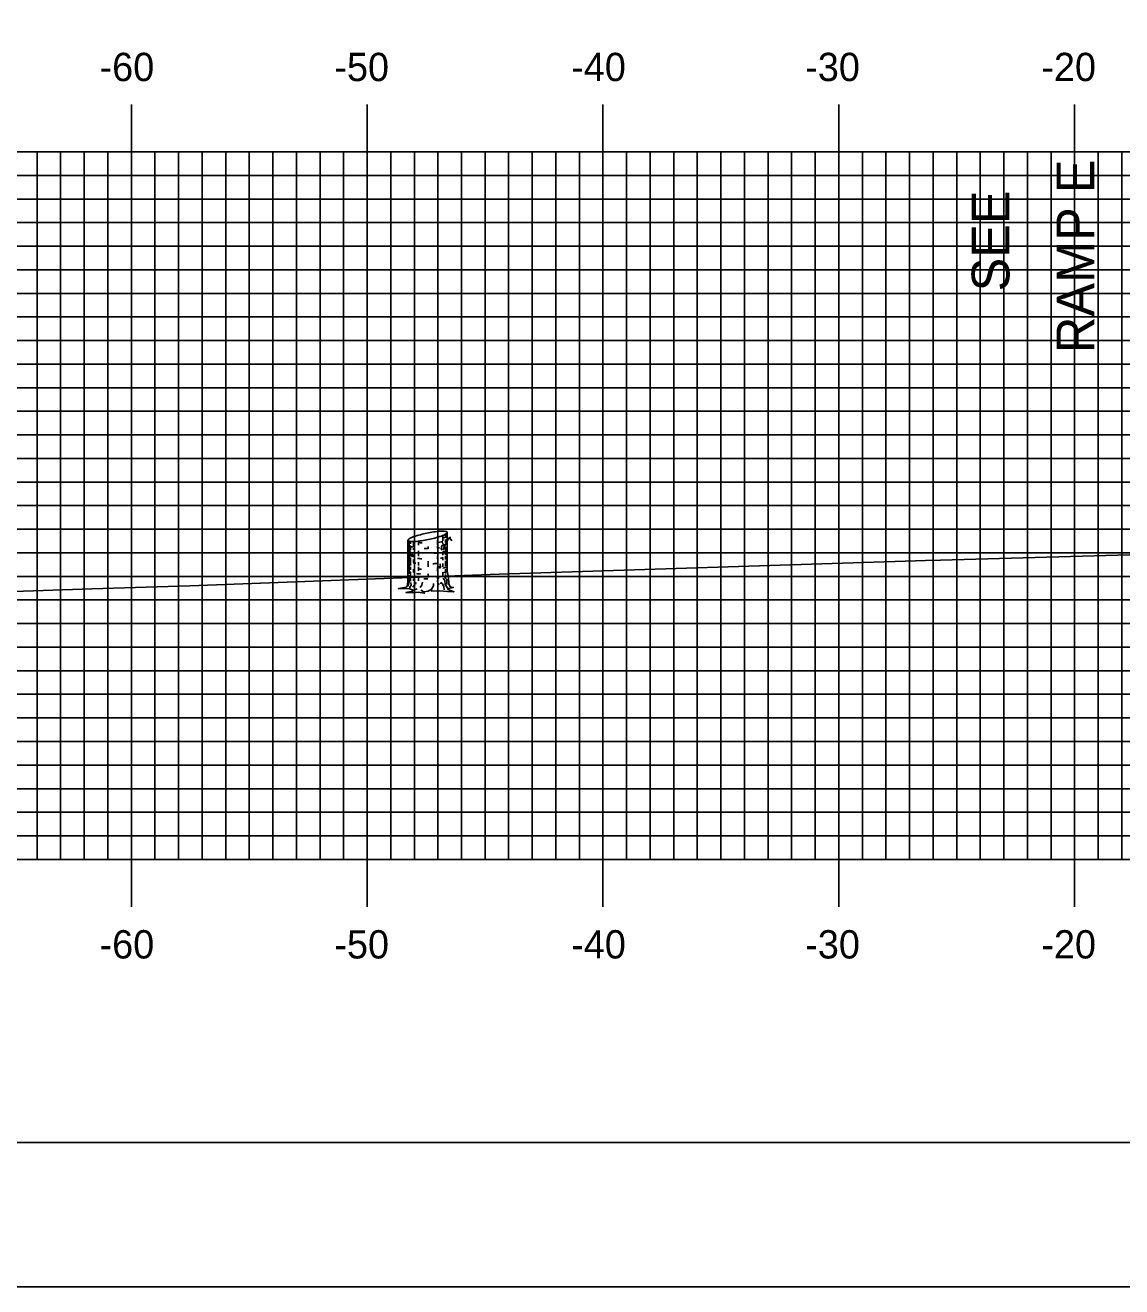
# Model space of a CAD drawing. Extents: x 1666 to 2009, y -1658 to -1438.
# Drawn here: x 1767.2 to 1813.7, y -1657.7 to -1604.2 of the extents above; entities that cross this region are included whole.
import ezdxf

# ---------------------------------------------------------------- set-up
doc = ezdxf.new("R2010")
doc.units = 0
for name, color, linetype in [('ANNOTATION', 7, 'Continuous'), ('BORDER', 7, 'Continuous'), ('H_V ANNOTATION', 7, 'Continuous'), ('M_Trees_Conifer_Pay', 7, 'Continuous'), ('MAJOR', 7, 'Continuous'), ('MINOR', 7, 'Continuous'), ('PLOT BOUNDARY', 7, 'Continuous'), ('S_Roadway_Centerline', 7, 'Continuous')]:
    doc.layers.add(name, color=color, linetype=linetype)

msp = doc.modelspace()

# ---------------------------------------------------------------- linework, layer by layer
at = {"layer": 'BORDER'}
msp.add_lwpolyline([(1682.074, -1651.604), (2002.074, -1651.604), (2002.074, -1441.604), (1682.074, -1441.604)], close=True, dxfattribs=at)
at = {"layer": 'M_Trees_Conifer_Pay'}
for p, q in [((1784.88, -1625.871), (1784.88, -1626.095)), ((1784.998, -1625.81), (1784.998, -1625.973)), ((1785.069, -1627.385), (1785.069, -1625.738)), ((1783.405, -1627.795), (1783.405, -1626.074)), ((1783.452, -1626.111), (1783.452, -1626.582)), ((1783.511, -1626.122), (1783.511, -1626.22)), ((1783.511, -1626.294), (1783.511, -1626.498)), ((1783.511, -1626.556), (1783.511, -1626.755)), ((1783.636, -1626.13), (1783.636, -1626.362)), ((1783.636, -1626.403), (1783.636, -1626.477)), ((1783.856, -1626.11), (1783.856, -1626.278)), ((1783.856, -1626.515), (1783.856, -1626.751)), ((1784.262, -1626.341), (1784.262, -1626.436)), ((1784.652, -1626.068), (1784.652, -1626.267)), ((1784.652, -1626.325), (1784.652, -1626.413)), ((1784.88, -1626.183), (1784.88, -1626.23)), ((1784.88, -1626.566), (1784.88, -1626.698)), ((1784.937, -1626.366), (1784.886, -1626.426)), ((1784.998, -1626.041), (1784.998, -1626.169)), ((1784.998, -1626.356), (1784.998, -1626.692)), ((1783.452, -1626.646), (1783.452, -1626.955)), ((1783.452, -1627.002), (1783.452, -1627.494)), ((1783.511, -1626.803), (1783.511, -1627.139)), ((1783.636, -1626.881), (1783.636, -1627.019)), ((1783.856, -1626.996), (1783.856, -1627.148)), ((1784.262, -1626.955), (1784.262, -1627.029)), ((1784.262, -1627.054), (1784.262, -1627.202)), ((1784.652, -1626.761), (1784.652, -1626.866)), ((1784.88, -1626.808), (1784.88, -1626.918)), ((1784.88, -1627.054), (1784.88, -1627.196)), ((1784.998, -1626.728), (1784.998, -1626.891)), ((1784.998, -1626.938), (1784.998, -1627.155)), ((1783.452, -1627.548), (1783.452, -1627.795)), ((1783.511, -1627.192), (1783.511, -1627.328)), ((1783.511, -1627.427), (1783.511, -1627.805)), ((1783.636, -1627.291), (1783.636, -1627.433)), ((1783.856, -1627.192), (1783.856, -1627.365)), ((1784.262, -1627.494), (1784.262, -1627.647)), ((1784.652, -1627.233), (1784.652, -1627.379)), ((1784.652, -1627.612), (1784.652, -1627.7)), ((1784.88, -1627.423), (1784.88, -1627.595)), ((1784.998, -1627.186), (1784.998, -1627.26)), ((1784.998, -1627.301), (1784.998, -1627.474)), ((1783.636, -1627.694), (1783.636, -1627.789)), ((1783.636, -1628.188), (1783.799, -1628.125)), ((1783.856, -1627.642), (1783.856, -1627.795)), ((1784.073, -1628.253), (1783.947, -1628.188))]:
    msp.add_line(p, q, dxfattribs=at)
for points in [[(1784.886, -1626.24), (1784.923, -1626.314), (1784.97, -1626.257), (1785.028, -1626.189), (1785.12, -1625.995), (1785.185, -1625.948), (1785.216, -1625.942)], [(1785.115, -1626.007), (1785.191, -1625.999), (1785.263, -1626.099)], [(1784.853, -1626.278), (1784.822, -1626.362), (1784.818, -1626.43), (1784.849, -1626.494)], [(1784.901, -1626.494), (1784.937, -1626.366), (1785.001, -1626.251), (1785.032, -1626.183), (1785.101, -1626.037)], [(1783.584, -1626.768), (1783.578, -1626.673), (1783.622, -1626.696), (1783.622, -1626.79)], [(1784.723, -1627.167), (1784.736, -1627.244), (1784.783, -1627.233), (1784.771, -1627.066)], [(1785.069, -1627.385), (1785.12, -1627.647), (1785.137, -1627.921), (1785.195, -1628.046), (1785.33, -1628.077), (1785.1, -1628.114), (1785.1, -1628.114), (1785.106, -1628.162), (1785.353, -1628.256), (1785.079, -1628.24), (1784.723, -1628.219), (1784.402, -1628.23), (1784.408, -1628.147), (1784.26, -1628.23), (1784.073, -1628.253), (1784.097, -1628.32), (1783.83, -1628.277), (1783.609, -1628.304), (1783.317, -1628.287), (1783.605, -1628.23), (1783.636, -1628.188), (1783.473, -1628.131), (1783.237, -1628.12), (1782.996, -1628.12), (1783.338, -1628.062), (1783.379, -1627.982), (1783.405, -1627.795)], [(1784.995, -1627.528), (1785.001, -1627.673), (1785.048, -1627.742), (1785.059, -1627.941)], [(1783.453, -1627.843), (1783.432, -1627.921), (1783.412, -1628.015)], [(1783.531, -1627.863), (1783.537, -1627.978), (1783.484, -1628.067), (1783.473, -1628.131)], [(1783.694, -1627.836), (1783.694, -1627.968), (1783.605, -1628.067)], [(1783.92, -1628.077), (1783.988, -1627.982), (1784.015, -1627.843)], [(1784.408, -1628.147), (1784.483, -1628.005), (1784.492, -1627.904)], [(1784.659, -1627.778), (1784.67, -1627.904), (1784.744, -1627.948)], [(1784.937, -1628.167), (1784.923, -1628.03), (1784.849, -1627.9)], [(1784.896, -1627.673), (1784.97, -1627.778), (1784.975, -1627.952), (1785.1, -1628.114)]]:
    msp.add_lwpolyline(points, dxfattribs=at)
for centre, radius, start, end in [((1783.594, -1626.224), 0.251, 124.2194, 132.3887), ((1783.904, -1626.68), 0.802, 108.0594, 124.2194), ((1785.261, -1630.841), 5.179, 101.7194, 108.0594), ((1785.261, -1630.841), 5.179, 95.3794, 101.7194), ((1783.214, -1620.971), 5.179, 281.7194, 288.0594), ((1784.851, -1626.483), 0.802, 79.2194, 95.3794), ((1784.571, -1625.132), 0.802, 288.0594, 304.2194), ((1784.738, -1625.425), 0.571, 284.4317, 292.4132), ((1784.954, -1625.942), 0.251, 71.0501, 79.2194), ((1784.88, -1625.588), 0.251, 304.2194, 312.3887), ((1784.938, -1625.77), 0.172, 300, 311.2506), ((1785.009, -1625.782), 0.0817, 56.7194, 71.0501), ((1784.994, -1625.713), 0.0817, 312.3887, 326.7194), ((1785.01, -1625.852), 0.0624, 311.2506, 330), ((1785.025, -1625.758), 0.0527, 46.923, 56.7194), ((1785.039, -1625.742), 0.0314, 34.2194, 46.923), ((1785.018, -1625.729), 0.0527, 326.7194, 336.5158), ((1785.026, -1625.862), 0.0441, 330, 343.9485), ((1785.026, -1626.016), 0.0441, 330, 343.9485), ((1785.043, -1625.74), 0.0264, 23.4074, 34.2194), ((1785.047, -1625.738), 0.0226, 11.7194, 23.4074), ((1785.038, -1625.737), 0.0314, 336.5158, 349.2194), ((1785.036, -1625.865), 0.0334, 343.9485, 354.2151), ((1785.036, -1626.019), 0.0334, 343.9485, 354.2151), ((1785.047, -1625.738), 0.0226, 0.0315, 11.7194), ((1785.043, -1625.738), 0.0264, 349.2194, 0.0315), ((1783.437, -1626.252), 0.0334, 163.9485, 180), ((1783.437, -1626.252), 0.0334, 180, 196.0515), ((1783.432, -1626.074), 0.0264, 169.2194, 180.0315), ((1783.428, -1626.074), 0.0226, 180.0315, 191.7194), ((1783.448, -1626.249), 0.0441, 196.0515, 210), ((1783.437, -1626.075), 0.0314, 156.5158, 169.2194), ((1783.428, -1626.074), 0.0226, 191.7194, 203.4074), ((1783.431, -1626.072), 0.0264, 203.4074, 214.2194), ((1783.456, -1626.083), 0.0527, 146.7194, 156.5158), ((1783.436, -1626.07), 0.0314, 214.2194, 226.923), ((1783.464, -1626.24), 0.0624, 210, 228.7494), ((1783.48, -1626.099), 0.0817, 132.3887, 146.7194), ((1783.45, -1626.054), 0.0527, 226.923, 236.7194), ((1783.466, -1626.03), 0.0817, 236.7194, 251.0501), ((1783.536, -1626.157), 0.172, 228.7494, 240), ((1783.521, -1625.87), 0.251, 251.0501, 259.2194), ((1783.735, -1625.812), 0.571, 240, 240.3367), ((1783.737, -1626.023), 0.571, 240, 247.0587), ((1783.624, -1625.329), 0.802, 259.2194, 275.3794), ((1783.735, -1625.812), 0.571, 246.8597, 257.9846), ((1783.214, -1620.971), 5.179, 275.3794, 281.7194), ((1784.238, -1622.062), 4.124, 264.6955, 266.7331), ((1784.236, -1622.295), 4.124, 268.0751, 270), ((1784.236, -1622.295), 4.124, 270, 270.3581), ((1784.236, -1622.295), 4.124, 275.7849, 277.0558), ((1784.238, -1622.062), 4.124, 276.238, 278.1032), ((1784.738, -1625.579), 0.571, 278.1032, 284.3667), ((1784.738, -1626.023), 0.571, 284.4493, 297.0429), ((1784.738, -1625.579), 0.571, 297.0237, 300), ((1784.938, -1625.924), 0.172, 300, 311.2506), ((1785.01, -1626.007), 0.0624, 311.2506, 330), ((1785.036, -1626.463), 0.0334, 343.9485, 354.2151), ((1783.437, -1626.699), 0.0334, 163.9485, 180), ((1783.437, -1626.699), 0.0334, 180, 196.0515), ((1783.437, -1626.909), 0.0334, 163.9485, 180), ((1783.437, -1626.909), 0.0334, 180, 196.0515), ((1783.448, -1626.696), 0.0441, 196.0515, 210), ((1783.448, -1626.906), 0.0441, 196.0515, 210), ((1783.464, -1626.687), 0.0624, 210, 228.7494), ((1783.464, -1626.897), 0.0624, 210, 228.7494), ((1783.536, -1626.604), 0.172, 228.7494, 240), ((1783.536, -1626.814), 0.172, 228.7494, 240), ((1783.735, -1626.259), 0.571, 240, 240.3367), ((1783.735, -1626.469), 0.571, 240, 246.8597), ((1783.735, -1626.469), 0.571, 259.2707, 261.8968), ((1784.236, -1622.951), 4.124, 261.8968, 263.1474), ((1784.236, -1622.741), 4.124, 264.081, 266.6676), ((1784.236, -1622.951), 4.124, 270, 270.3581), ((1784.236, -1622.951), 4.124, 273.1493, 275.4569), ((1784.237, -1622.506), 4.124, 273.7052, 275.9504), ((1784.236, -1622.741), 4.124, 277.6125, 278.1032), ((1784.737, -1626.259), 0.571, 278.1032, 286.9296), ((1784.737, -1626.259), 0.571, 297.1896, 300), ((1784.737, -1626.469), 0.571, 297.1896, 300), ((1784.936, -1626.604), 0.172, 300, 311.2506), ((1784.936, -1626.814), 0.172, 300, 311.2506), ((1785.009, -1626.687), 0.0624, 311.2506, 330), ((1785.009, -1626.897), 0.0624, 311.2506, 330), ((1785.024, -1626.696), 0.0441, 330, 343.9485), ((1785.024, -1626.906), 0.0441, 330, 343.9485), ((1785.035, -1626.699), 0.0334, 343.9485, 354.2151), ((1785.035, -1626.909), 0.0334, 343.9485, 354.2151), ((1783.437, -1627.145), 0.0334, 163.9485, 180), ((1783.437, -1627.145), 0.0334, 180, 196.0515), ((1783.437, -1627.343), 0.0334, 163.9485, 180), ((1783.437, -1627.539), 0.0334, 163.9485, 180), ((1783.437, -1627.539), 0.0334, 180, 196.0515), ((1783.448, -1627.142), 0.0441, 196.0515, 210), ((1783.448, -1627.536), 0.0441, 196.0515, 210), ((1783.464, -1627.133), 0.0624, 210, 228.7494), ((1783.464, -1627.527), 0.0624, 210, 228.7494), ((1783.536, -1627.051), 0.172, 228.7494, 240), ((1783.536, -1627.444), 0.172, 228.7494, 240), ((1783.735, -1626.706), 0.571, 240, 246.8597), ((1783.724, -1626.897), 0.571, 241.2369, 248.0268), ((1783.735, -1627.099), 0.571, 240, 246.8597), ((1784.236, -1623.386), 4.124, 263.4991, 265.8397), ((1784.236, -1623.188), 4.124, 264.716, 266.3193), ((1784.737, -1626.706), 0.571, 285.3983, 297.1896), ((1784.737, -1627.099), 0.571, 288.5067, 297.2721), ((1784.737, -1626.903), 0.571, 289.2907, 300), ((1784.936, -1627.248), 0.172, 300, 311.2506), ((1785.009, -1627.331), 0.0624, 311.2506, 330), ((1785.024, -1627.34), 0.0441, 330, 343.9485), ((1785.035, -1627.343), 0.0334, 343.9485, 354.2151), ((1783.437, -1627.759), 0.0334, 163.9485, 180), ((1783.437, -1627.759), 0.0334, 180, 196.0515), ((1783.448, -1627.756), 0.0441, 196.0515, 210), ((1783.464, -1627.747), 0.0624, 210, 228.7494), ((1783.536, -1627.664), 0.172, 228.7494, 240), ((1783.735, -1627.319), 0.571, 240, 244.5314), ((1784.236, -1623.802), 4.124, 262.4438, 263.512), ((1784.236, -1623.581), 4.124, 267.8117, 270), ((1784.236, -1623.581), 4.124, 270, 270.1328), ((1784.236, -1623.581), 4.124, 275.7849, 276.7896), ((1784.236, -1623.802), 4.124, 277.3684, 278.1032), ((1784.737, -1627.319), 0.571, 278.1032, 281.637), ((1784.936, -1627.664), 0.172, 300, 311.2506), ((1785.009, -1627.747), 0.0624, 311.2506, 330), ((1785.024, -1627.756), 0.0441, 330, 343.9485), ((1785.035, -1627.759), 0.0334, 343.9485, 354.2151)]:
    msp.add_arc(centre, radius, start, end, dxfattribs=at)
at = {"layer": 'MAJOR'}
for p, q in [((1771.674, -1607.6), (1771.674, -1609.604)), ((1781.674, -1607.6), (1781.674, -1609.604)), ((1791.674, -1607.6), (1791.674, -1609.604)), ((1801.674, -1607.6), (1801.674, -1609.604)), ((1811.674, -1607.6), (1811.674, -1609.604)), ((1691.674, -1609.604), (1971.674, -1609.604)), ((1691.674, -1609.604), (1971.674, -1609.604)), ((1771.674, -1639.604), (1771.674, -1609.604)), ((1781.674, -1639.604), (1781.674, -1609.604)), ((1791.674, -1639.604), (1791.674, -1609.604)), ((1801.674, -1639.604), (1801.674, -1609.604)), ((1811.674, -1639.604), (1811.674, -1609.604)), ((1691.674, -1614.604), (1971.674, -1614.604)), ((1691.674, -1619.604), (1971.674, -1619.604)), ((1691.674, -1624.604), (1971.674, -1624.604)), ((1691.674, -1629.604), (1971.674, -1629.604)), ((1691.674, -1634.604), (1971.674, -1634.604)), ((1691.674, -1639.604), (1971.674, -1639.604)), ((1691.674, -1639.604), (1971.674, -1639.604)), ((1771.674, -1641.608), (1771.674, -1639.604)), ((1781.674, -1641.608), (1781.674, -1639.604)), ((1791.674, -1641.608), (1791.674, -1639.604)), ((1801.674, -1641.608), (1801.674, -1639.604)), ((1811.674, -1641.608), (1811.674, -1639.604))]:
    msp.add_line(p, q, dxfattribs=at)
at = {"layer": 'MINOR'}
for p, q in [((1767.674, -1639.604), (1767.674, -1609.604)), ((1768.674, -1639.604), (1768.674, -1609.604)), ((1769.674, -1639.604), (1769.674, -1609.604)), ((1770.674, -1639.604), (1770.674, -1609.604)), ((1772.674, -1639.604), (1772.674, -1609.604)), ((1773.674, -1639.604), (1773.674, -1609.604)), ((1774.674, -1639.604), (1774.674, -1609.604)), ((1775.674, -1639.604), (1775.674, -1609.604)), ((1776.674, -1639.604), (1776.674, -1609.604)), ((1777.674, -1639.604), (1777.674, -1609.604)), ((1778.674, -1639.604), (1778.674, -1609.604)), ((1779.674, -1639.604), (1779.674, -1609.604)), ((1780.674, -1639.604), (1780.674, -1609.604)), ((1782.674, -1639.604), (1782.674, -1609.604)), ((1783.674, -1639.604), (1783.674, -1609.604)), ((1784.674, -1639.604), (1784.674, -1609.604)), ((1785.674, -1639.604), (1785.674, -1609.604)), ((1786.674, -1639.604), (1786.674, -1609.604)), ((1787.674, -1639.604), (1787.674, -1609.604)), ((1788.674, -1639.604), (1788.674, -1609.604)), ((1789.674, -1639.604), (1789.674, -1609.604)), ((1790.674, -1639.604), (1790.674, -1609.604)), ((1792.674, -1639.604), (1792.674, -1609.604)), ((1793.674, -1639.604), (1793.674, -1609.604)), ((1794.674, -1639.604), (1794.674, -1609.604)), ((1795.674, -1639.604), (1795.674, -1609.604)), ((1796.674, -1639.604), (1796.674, -1609.604)), ((1797.674, -1639.604), (1797.674, -1609.604)), ((1798.674, -1639.604), (1798.674, -1609.604)), ((1799.674, -1639.604), (1799.674, -1609.604)), ((1800.674, -1639.604), (1800.674, -1609.604)), ((1802.674, -1639.604), (1802.674, -1609.604)), ((1803.674, -1639.604), (1803.674, -1609.604)), ((1804.674, -1639.604), (1804.674, -1609.604)), ((1805.674, -1639.604), (1805.674, -1609.604)), ((1806.674, -1639.604), (1806.674, -1609.604)), ((1807.674, -1639.604), (1807.674, -1609.604)), ((1808.674, -1639.604), (1808.674, -1609.604)), ((1809.674, -1639.604), (1809.674, -1609.604)), ((1810.674, -1639.604), (1810.674, -1609.604)), ((1812.674, -1639.604), (1812.674, -1609.604)), ((1813.674, -1639.604), (1813.674, -1609.604)), ((1691.674, -1610.604), (1971.674, -1610.604)), ((1691.674, -1611.604), (1971.674, -1611.604)), ((1691.674, -1612.604), (1971.674, -1612.604)), ((1691.674, -1613.604), (1971.674, -1613.604)), ((1691.674, -1615.604), (1971.674, -1615.604)), ((1691.674, -1616.604), (1971.674, -1616.604)), ((1691.674, -1617.604), (1971.674, -1617.604)), ((1691.674, -1618.604), (1971.674, -1618.604)), ((1691.674, -1620.604), (1971.674, -1620.604)), ((1691.674, -1621.604), (1971.674, -1621.604)), ((1691.674, -1622.604), (1971.674, -1622.604)), ((1691.674, -1623.604), (1971.674, -1623.604)), ((1691.674, -1625.604), (1971.674, -1625.604)), ((1691.674, -1626.604), (1971.674, -1626.604)), ((1691.674, -1627.604), (1971.674, -1627.604)), ((1691.674, -1628.604), (1971.674, -1628.604)), ((1691.674, -1630.604), (1971.674, -1630.604)), ((1691.674, -1631.604), (1971.674, -1631.604)), ((1691.674, -1632.604), (1971.674, -1632.604)), ((1691.674, -1633.604), (1971.674, -1633.604)), ((1691.674, -1635.604), (1971.674, -1635.604)), ((1691.674, -1636.604), (1971.674, -1636.604)), ((1691.674, -1637.604), (1971.674, -1637.604)), ((1691.674, -1638.604), (1971.674, -1638.604))]:
    msp.add_line(p, q, dxfattribs=at)
at = {"layer": 'PLOT BOUNDARY'}
msp.add_lwpolyline([(1665.887, -1657.723), (2005.887, -1657.723), (2005.887, -1437.723), (1665.887, -1437.723)], close=True, dxfattribs=at)
at = {"layer": 'S_Roadway_Centerline'}
msp.add_lwpolyline([(1691.674, -1630.506), (1698.876, -1630.25), (1711.689, -1629.994), (1715.82, -1629.915), (1721.305, -1629.719), (1734.01, -1629.339), (1742.956, -1628.959), (1752.121, -1628.587), (1764.61, -1628.321), (1770.004, -1628.13), (1774.157, -1627.999), (1787.265, -1627.509), (1804.928, -1626.941), (1805.349, -1626.927), (1805.982, -1626.922), (1819.016, -1626.554), (1823.37, -1626.71), (1833.959, -1626.589), (1840.695, -1626.449), (1849.589, -1626.314), (1856.031, -1626.306), (1858.435, -1626.306), (1864.854, -1626.2), (1877.053, -1626.205)], dxfattribs=at)

# ---------------------------------------------------------------- texts
at = {"layer": 'ANNOTATION'}
for s, p in [('RAMP E', (1812.509, -1618.135)), ('SEE', (1808.909, -1615.521))]:
    msp.add_text(s, height=1.6, rotation=90, dxfattribs=at).set_placement(p)
at = {"layer": 'H_V ANNOTATION'}
for s, p in [('-60', (1770.325, -1606.604)), ('-50', (1780.282, -1606.604)), ('-40', (1790.325, -1606.604)), ('-30', (1800.25, -1606.604)), ('-20', (1810.261, -1606.604)), ('-60', (1770.325, -1643.804)), ('-50', (1780.282, -1643.804)), ('-40', (1790.325, -1643.804)), ('-30', (1800.25, -1643.804)), ('-20', (1810.261, -1643.804))]:
    msp.add_text(s, height=1.2, dxfattribs=at).set_placement(p)

doc.saveas('drawing.dxf')
